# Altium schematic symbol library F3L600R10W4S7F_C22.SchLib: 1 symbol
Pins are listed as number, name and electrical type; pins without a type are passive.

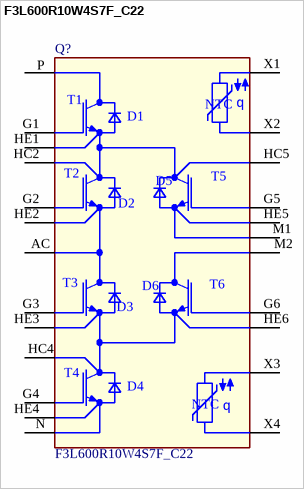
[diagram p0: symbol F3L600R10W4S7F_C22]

## F3L600R10W4S7F_C22
designator Q?
EasyPACK Module with TRENCHSTOP IGBT7 and CoolSiC Schottky Diode and PressFIT / NTC; Manufacturer: Infineon Technology
pins: AC1, AC2, AC3, AC4, AC5, AC6, AC7, AC8, AC9, AC10, AC11, AC12, AC13, AC14, G1, G2, G3, G4, G5, G6, HC2, HC4_1, HC4_2, HC5, HE1, HE2, HE3, HE4, HE5, HE6, M1_1, M1_2, M1_3, M1_4, M1_5, M1_6, M1_7, M1_8, M1_9, M1_10, M2_1, M2_2, M2_3, M2_4, M2_5, M2_6, M2_7, M2_8, N1, N2, N3, N4, N5, N6, N7, N8, N9, N10, N11, P_1, P_2, P_3, P_4, P_5, P_6, P_7, P_8, P_9, P_10, P_11, P_12, X1, X2, X3, X4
